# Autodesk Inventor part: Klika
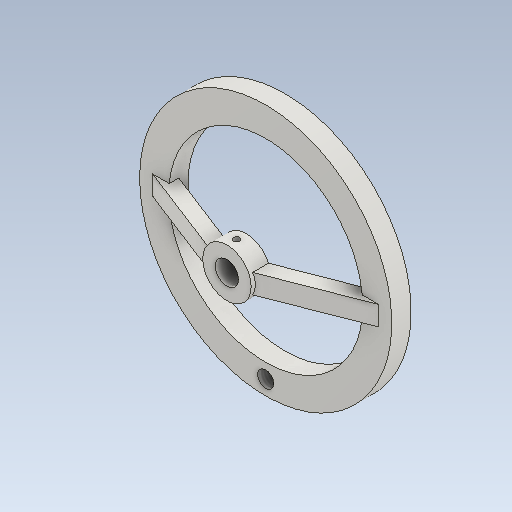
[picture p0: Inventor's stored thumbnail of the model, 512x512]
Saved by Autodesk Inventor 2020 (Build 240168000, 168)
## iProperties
Created: 2025-03
Part Number: Klika
Material: Ocel
Document SubType Name: Modeling
Designer: doma
Density: 7.85 g/cm^3
Appearance: Ocel
Mass: 501.292 g
Surface Area: 228.74 cm^2
Volume: 63.8588 cm^3
Author: doma
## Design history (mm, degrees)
sketch "Náčrt1"
  geometry: C1 r 6 at (0, 0); C2 r 12.5 at (0, 0); 1 further point
  constraints: 2 centre point, 2 coincident
  dimensions: "d0" = 12 diameter of C1; "d1" = 25 diameter of C2
extrude "Vysunutí1" new body sketch "Náčrt1" distance "d2" = 10; taper "d3" = 0 deg
node "Pracovní rovina1"
  node "Pracovní bod1"
sketch "Náčrt2"
  geometry: L1 (12.5, 0)-(-12.5, 0) reference; L2 (0, 0)-(0, -10); 1 further point
  constraints: 2 end point, 2 midpoint, 1 vertical
hole "Díra1" sketch "Náčrt2" at (0, -5) diameter "d4" = 3.242; stored, may be unused: countersink angle "d8" = 90 deg, drill point angle "d10" = 118 deg; dims "d5" = 8, "d6" = 4, "d7" = 2, "d9" = 11.8
node "Pracovní rovina3"
sketch "Náčrt3"
  geometry: C1 r 12.5 at (0, 0) reference; C2 r 50 at (0, 0); C3 r 65 at (0, 0); 1 further point
  constraints: 2 centre point, 2 coincident
  dimensions: "d13" = 100 diameter of C2; "d14" = 130 diameter of C3
extrude "Vysunutí2" join sketch "Náčrt3" distance "d15" = 10; taper "d16" = 0 deg
sketch "Náčrt4"
  geometry: L1 (12.5, 0)-(12.5, 10) reference; L2 (50, -20)-(50, -10) reference; L3 (12.5, 0)-(-12.5, 0) reference; L4 (11.382, 0)-(50, -15); L5 (14.16, 7.153)-(69.364, -14.289); L6 (69.364, -14.289)-(94.082, -27.474); L7 (50, -15)-(62.994, -10.891); L8 (14.16, 7.153)-(-19.43, 20.2); L9 (11.382, 0)-(2.666, 3.385); L10 (8.469, 1.131)-(8.469, 9.363); 1 further point
  constraints: 14 end point, 4 point on line, 2 parallel, 1 midpoint, 1 vertical
extrude "Vysunutí5" join sketch "Náčrt4" stored distance "d29" = 10; taper "d30" = 0 deg
mirror "Zrcadlit3"
sketch "Náčrt5"
  geometry: 2 further points
hole "Díra2" sketch "Náčrt5" at (0, -57.5) diameter "d32" = 8.376; stored, may be unused: countersink angle "d36" = 90 deg, drill point angle "d38" = 118 deg; dims "d33" = 20, "d34" = 4, "d35" = 2, "d37" = 27.3
node "Těleso1"
